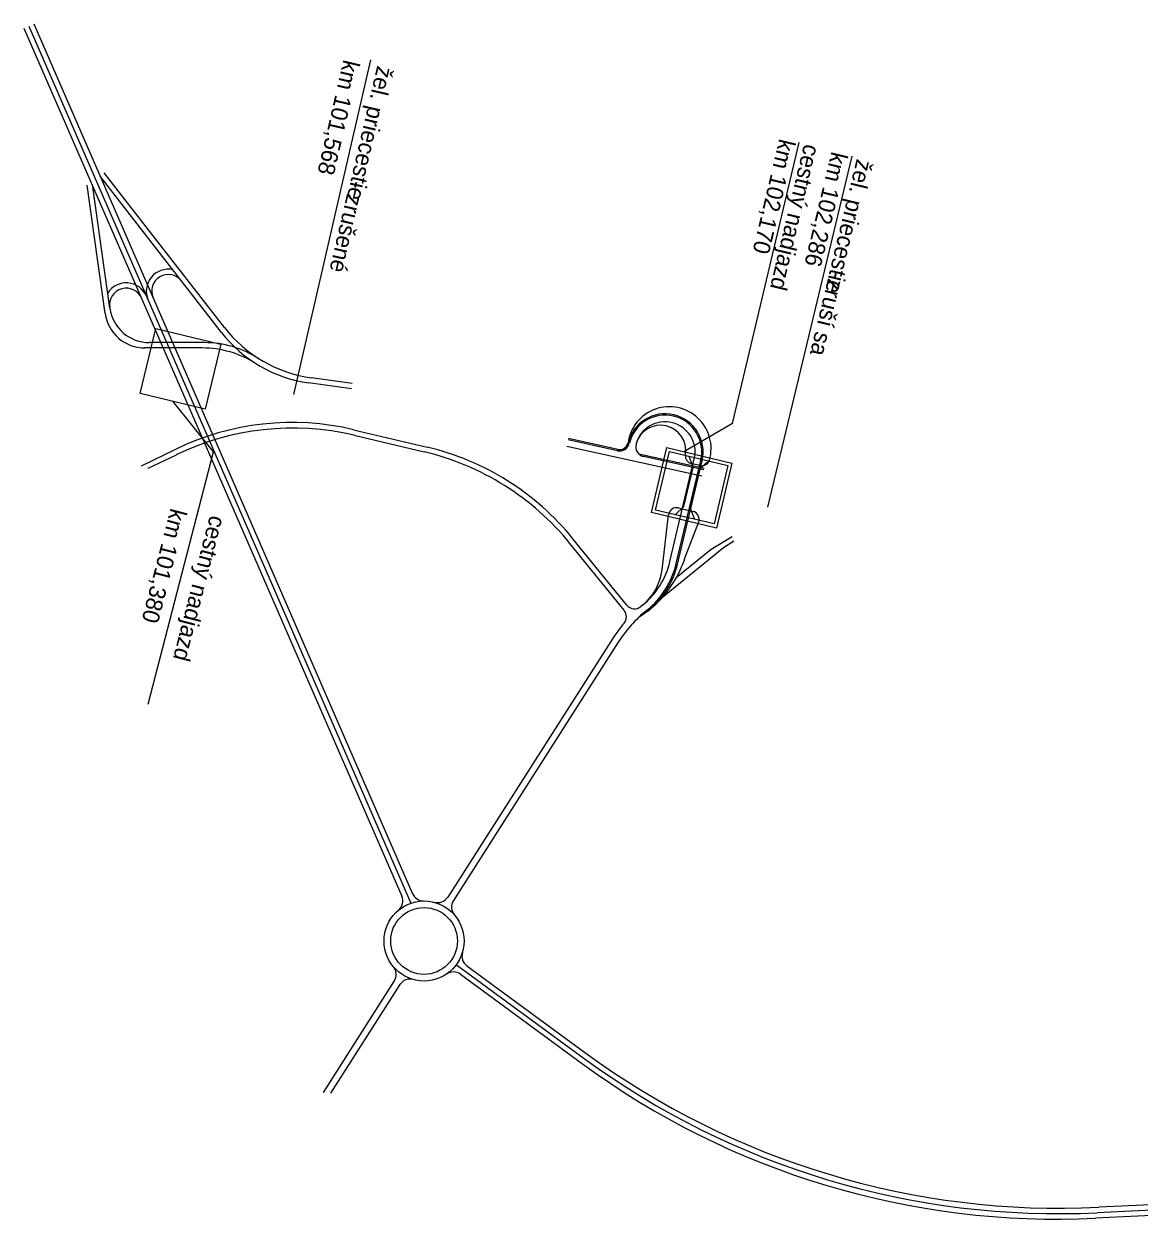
# Model space of a CAD drawing. Extents: x -566241 to -446826, y -1330151 to -1274078.
# Drawn here: x -529700 to -528029, y -1281586 to -1279796 of the extents above; entities that cross this region are included whole.
import ezdxf

# ---------------------------------------------------------------- set-up
doc = ezdxf.new("R2010")
doc.units = 0
for name, color, linetype in [('1-POPIS', 7, 'Continuous'), ('10_cesty_plochy', 7, 'Continuous'), ('priecestia', 7, 'Continuous')]:
    doc.layers.add(name, color=color, linetype=linetype)

msp = doc.modelspace()

# ---------------------------------------------------------------- linework, layer by layer
at = {"layer": '1-POPIS'}
for p, q in [((-529416.1, -1280436.5), (-529476.9, -1280360.8)), ((-529513.8, -1280814.5), (-529416.1, -1280436.5)), ((-528703.7, -1280443.1), (-528697.5, -1280460)), ((-528687.7, -1280462.3), (-528674.5, -1280450)), ((-528711.3, -1280518.4), (-528697.5, -1280460)), ((-528701.6, -1280520.7), (-528687.7, -1280462.3)), ((-528711.3, -1280518.4), (-528724.5, -1280530.7)), ((-528701.6, -1280520.7), (-528695.3, -1280537.6))]:
    msp.add_line(p, q, dxfattribs=at)
for points in [[(-529502.2, -1280251.9), (-529405, -1280275.3), (-529428.3, -1280372.5), (-529525.6, -1280349.1)], [(-528736.6, -1280430.2), (-528639.3, -1280453.3), (-528662.4, -1280550.6), (-528759.7, -1280527.5)], [(-528732.9, -1280436.2), (-528645.3, -1280457), (-528666.1, -1280544.5), (-528753.7, -1280523.8)]]:
    msp.add_lwpolyline(points, close=True, dxfattribs=at)
at = {"layer": '10_cesty_plochy'}
for p, q in [((-529685.3, -1279795.6), (-529117.8, -1281098.3)), ((-529700, -1279802), (-529133.7, -1281101.8)), ((-529692.7, -1279798.8), (-529120.3, -1281112.4)), ((-529403.9, -1280257.8), (-529585.9, -1280023.7)), ((-529399.6, -1280250.3), (-529579.6, -1280018.8)), ((-529578.2, -1280229.3), (-529605.1, -1280037.2)), ((-529571.3, -1280221.3), (-529597.2, -1280036.1)), ((-529429.4, -1280273), (-529511.8, -1280273)), ((-529432.9, -1280281), (-529518.8, -1280281)), ((-529209.4, -1280342), (-529273.4, -1280333.2)), ((-529208.3, -1280334.1), (-529269.1, -1280325.7)), ((-529206, -1280403.4), (-529095.9, -1280429.4)), ((-529205.1, -1280411.8), (-529100.4, -1280436.6)), ((-529473, -1280432.8), (-529524.5, -1280457.8)), ((-529472.1, -1280441.3), (-529514.2, -1280461.7)), ((-528796.8, -1280666.1), (-528877.5, -1280566.6)), ((-528638.7, -1280563.9), (-528670.2, -1280582.6)), ((-528800.7, -1280673.9), (-528882, -1280573.7)), ((-528651.7, -1280580.5), (-528745.6, -1280656.7)), ((-528670.2, -1280582.6), (-528722.7, -1280625.3)), ((-528636.4, -1280570.3), (-528651.7, -1280580.5)), ((-528773.3, -1280666.3), (-528775.7, -1280668.2)), ((-528766.5, -1280673.7), (-528767, -1280674.1)), ((-528817, -1280715), (-529065, -1281103.4)), ((-528809.5, -1280721.7), (-529056.4, -1281108.6)), ((-529052.1, -1281204.6), (-528860.6, -1281345)), ((-529036.4, -1281206.1), (-528858.2, -1281336.9)), ((-529145.1, -1281228.9), (-529251.7, -1281395.9)), ((-529045.9, -1281219), (-528863.1, -1281353.2)), ((-529136.8, -1281234.5), (-529240.6, -1281397.1)), ((-527117, -1281528.3), (-528092, -1281576.1)), ((-527120.7, -1281520.5), (-528089.6, -1281568)), ((-527113.3, -1281536.2), (-528094.5, -1281584.2))]:
    msp.add_line(p, q, dxfattribs=at)
for radius in [60, 50]:
    msp.add_circle((-529100.5, -1281169.1), radius, dxfattribs=at)
for centre, radius, start, end in [((-529483.6, -1280196), 33, 78.6098, 203.5419), ((-529483.6, -1280196), 25, 37.8608, 203.5419), ((-529546.7, -1280216.5), 33, 23.5419, 147.2292), ((-529546.7, -1280216.5), 25, 23.5419, 187.9782), ((-529511.8, -1280213), 60, 187.9782, 270), ((-529518.8, -1280221), 60, 187.9782, 270), ((-529246, -1280135.1), 200, 217.8608, 262.1266), ((-529241.7, -1280127.6), 200, 217.8608, 262.1266), ((-529429.4, -1280423), 150, 57.563, 90), ((-529432.9, -1280431), 150, 57.7224, 90), ((-529298.2, -1280792.6), 400, 76.6768, 115.9149), ((-529297.3, -1280801), 400, 76.6768, 115.9149), ((-529192.6, -1280825.8), 400, 39.0722, 76.6768), ((-529188.1, -1280818.7), 400, 39.0722, 76.6768), ((-528640.9, -1280829.3), 200, 129.0722, 147.4503), ((-528812.3, -1280683.4), 15, 319.6532, 39.0722), ((-528785.1, -1280656.6), 15, 219.0722, 309.0722), ((-528648.5, -1280822.6), 200, 139.6532, 147.4503), ((-529150.2, -1281109), 18, 309.6236, 23.5419), ((-529101.3, -1281091.1), 18, 203.5419, 270.6086), ((-529080.2, -1281093.7), 18, 254.9161, 327.4503), ((-529041.3, -1281118.3), 18, 147.4503, 220.6159), ((-529025.8, -1281191.6), 18, 163.2026, 233.7314), ((-529160.2, -1281219.2), 18, 327.4503, 39.9845), ((-529121.6, -1281244.1), 18, 74.2848, 147.4503), ((-529056.6, -1281233.5), 18, 53.7314, 124.2601), ((-528148.3, -1280369.4), 1200, 233.7314, 272.8042), ((-528153.2, -1280385.7), 1200, 233.7314, 272.8042), ((-528150.7, -1280377.5), 1200, 233.7314, 272.8042)]:
    msp.add_arc(centre, radius, start, end, dxfattribs=at)
at = {"layer": 'priecestia'}
for p, q in [((-529295.6, -1280350.7), (-529180.1, -1279849.5)), ((-528638.3, -1280394.2), (-528538.4, -1279973.1)), ((-528585.6, -1280519.6), (-528459.3, -1279993.9)), ((-528638.3, -1280394.2), (-528711.4, -1280436.5)), ((-528810.8, -1280434.9), (-528884.6, -1280418.5)), ((-528810.4, -1280432.9), (-528884.2, -1280416.6)), ((-528684.4, -1280473.1), (-528886.8, -1280428.3)), ((-528680.8, -1280461.6), (-528778.6, -1280440)), ((-528681.5, -1280463.5), (-528771.8, -1280443.5)), ((-528732.2, -1280600.8), (-528695.7, -1280447)), ((-528722.6, -1280603.8), (-528686, -1280449.3)), ((-528721.9, -1280609.3), (-528684.1, -1280449.8)), ((-528687, -1280457.2), (-528699.5, -1280454.4)), ((-528744, -1280613.2), (-528734.1, -1280530.7)), ((-528709.3, -1280594.4), (-528689.1, -1280541.6)), ((-528765.2, -1280675.2), (-528778.8, -1280684.6))]:
    msp.add_line(p, q, dxfattribs=at)
msp.add_lwpolyline([(-528719.4, -1280520.5), (-528697.5, -1280525.7)], dxfattribs=at)
for centre, radius, start, end in [((-528733, -1280431.5), 62.5, 343.9502, 172.4603), ((-528739.5, -1280436.6), 57, 346.6724, 166.4608), ((-528739.5, -1280436.6), 55, 346.6724, 166.4608), ((-528739.5, -1280436.6), 45, 346.6724, 165.0492), ((-528746.2, -1280434.7), 38, 350.7949, 163.9508), ((-528807.6, -1280420.2), 15, 257.519, 346.4608), ((-528807.6, -1280420.2), 13, 257.519, 346.4608), ((-528768.5, -1280428.9), 15, 165.0492, 257.519), ((-528696.9, -1280442.7), 12, 170.7949, 257.519), ((-528684.4, -1280445.4), 12, 257.519, 343.9502), ((-528722.2, -1280532.2), 12, 76.6724, 173.1446), ((-528700.3, -1280537.4), 12, 339.0813, 76.6724), ((-528849, -1280573.2), 120, 309.0722, 346.6724), ((-528868.8, -1280543.1), 167.6, 311.9254, 342.1635), ((-528824.3, -1280603.5), 80.9, 309.0722, 353.1446), ((-528847.2, -1280574.3), 128, 309.0722, 346.6724), ((-528847.2, -1280574.3), 130, 309.0722, 346.6724)]:
    msp.add_arc(centre, radius, start, end, dxfattribs=at)

# ---------------------------------------------------------------- texts
at = {"layer": '1-POPIS'}
for s, p in [('km 101,380', (-529480, -1280519.9)), ('cestný nadjazd', (-529421, -1280530.4))]:
    msp.add_text(s, height=25, rotation=255.5073, dxfattribs=at).set_placement(p)
at = {"layer": 'priecestia'}
for s, rotation, p in [('km 101,568', 257.0224, (-529221.1, -1279848.2)), ('žel. priecestie', 257.0224, (-529170.5, -1279857.3)), ('km 102,170', 256.6545, (-528568.2, -1279966.6)), ('cestný nadjazd ', 256.6545, (-528531, -1279974.3)), ('km 102,286', 256.4868, (-528490, -1279985.8)), ('žel. priecestie', 256.4868, (-528452.2, -1279996.9)), ('- zrušené', 257.0224, (-529211.1, -1280029.1)), ('-zruší sa', 256.4868, (-528492.5, -1280164.8))]:
    msp.add_text(s, height=25, rotation=rotation, dxfattribs=at).set_placement(p)

doc.saveas('drawing.dxf')
